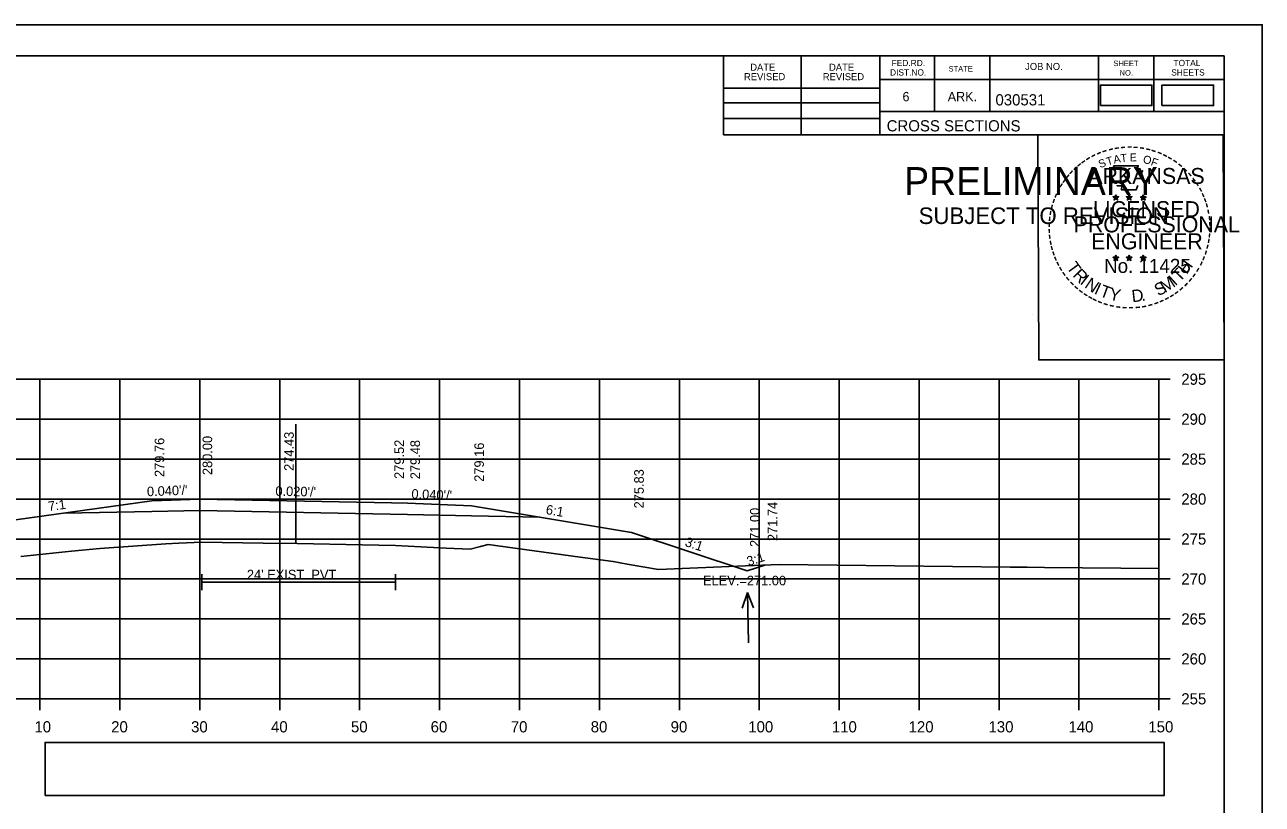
# Model space of a CAD drawing. Extents: x 285 to 4233, y -659 to 3710.
# Drawn here: x 1231.8 to 1386.6, y 288 to 385.6 of the extents above; entities that cross this region are included whole.
import ezdxf

# ---------------------------------------------------------------- set-up
doc = ezdxf.new("R2010")
doc.units = 0
for name, color, linetype in [('R_Alt Surface', 7, 'Continuous'), ('R_Axis', 7, 'Continuous'), ('R_Axis Annot', 7, 'Continuous'), ('R_Border', 7, 'Continuous'), ('R_Border PE', 7, 'Continuous'), ('R_Border Prem', 7, 'Continuous'), ('R_Exist Surface', 7, 'Continuous'), ('R_Fin Surface', 7, 'Continuous'), ('R_Grid', 7, 'Continuous'), ('R_No Plot', 7, 'Continuous'), ('R_Water', 7, 'Continuous'), ('R_Water Annot', 7, 'Continuous'), ('R_Xsect Elev', 7, 'Continuous'), ('R_Xsect Slope', 7, 'Continuous')]:
    doc.layers.add(name, color=color, linetype=linetype)

msp = doc.modelspace()

# ---------------------------------------------------------------- linework, layer by layer
at = {"layer": 'R_Alt Surface'}
for points in [[(1236.77, 324.46), (1247.68, 324.67), (1253.68, 324.79), (1253.68, 324.79), (1279.68, 324.27), (1287.68, 324.11), (1296.24, 323.94)], [(1253.95, 316.82), (1253.95, 314.82)], [(1278.15, 316.82), (1278.15, 314.82)], [(1253.95, 315.82), (1278.15, 315.82)]]:
    msp.add_lwpolyline(points, dxfattribs=at)
at = {"layer": 'R_Axis'}
for p, q in [((1373.68, 301.21), (1373.68, 341.21)), ((1375.08, 341.21), (1373.68, 341.21)), ((1375.08, 336.21), (1373.68, 336.21)), ((1375.08, 331.21), (1373.68, 331.21)), ((1375.08, 326.21), (1373.68, 326.21)), ((1375.08, 321.21), (1373.68, 321.21)), ((1375.08, 316.21), (1373.68, 316.21)), ((1375.08, 311.21), (1373.68, 311.21)), ((1375.08, 306.21), (1373.68, 306.21)), ((1073.68, 301.21), (1373.68, 301.21)), ((1233.68, 299.81), (1233.68, 301.21)), ((1243.68, 299.81), (1243.68, 301.21)), ((1253.68, 299.81), (1253.68, 301.21)), ((1263.68, 299.81), (1263.68, 301.21)), ((1273.68, 299.81), (1273.68, 301.21)), ((1283.68, 299.81), (1283.68, 301.21)), ((1293.68, 299.81), (1293.68, 301.21)), ((1303.68, 299.81), (1303.68, 301.21)), ((1313.68, 299.81), (1313.68, 301.21)), ((1323.68, 299.81), (1323.68, 301.21)), ((1333.68, 299.81), (1333.68, 301.21)), ((1343.68, 299.81), (1343.68, 301.21)), ((1353.68, 299.81), (1353.68, 301.21)), ((1363.68, 299.81), (1363.68, 301.21)), ((1373.68, 299.81), (1373.68, 301.21)), ((1375.08, 301.21), (1373.68, 301.21))]:
    msp.add_line(p, q, dxfattribs=at)
at = {"layer": 'R_Axis Annot'}
for points in [[(1366.36, 375.46), (1372.81, 375.46), (1372.81, 378.01), (1366.36, 378.01)], [(1374.05, 375.46), (1380.51, 375.46), (1380.51, 378.01), (1374.05, 378.01)], [(1234.32, 289.1), (1374.32, 289.1), (1374.32, 295.75), (1234.32, 295.75)]]:
    msp.add_lwpolyline(points, close=True, dxfattribs=at)
at = {"layer": 'R_Border'}
for p, q in [((1065.68, 381.67), (1381.86, 381.67)), ((1319.22, 371.79), (1319.22, 381.67)), ((1328.9, 371.79), (1328.9, 381.67)), ((1338.76, 381.67), (1338.76, 371.79)), ((1345.6, 381.67), (1345.6, 374.73)), ((1352.54, 381.67), (1352.54, 374.73)), ((1366.12, 381.67), (1366.12, 374.73)), ((1373.06, 381.67), (1373.06, 374.73)), ((1381.86, 176.21), (1381.86, 381.67)), ((1381.86, 378.73), (1338.76, 378.73)), ((1381.86, 378.75), (1381.86, 378.75)), ((1319.22, 377.65), (1338.76, 377.65)), ((1319.22, 375.79), (1338.76, 375.79)), ((1381.86, 374.73), (1338.76, 374.73)), ((1341.72, 374.73), (1381.86, 374.73)), ((1319.22, 373.85), (1338.76, 373.85)), ((1381.86, 371.79), (1319.22, 371.79))]:
    msp.add_line(p, q, dxfattribs=at)
at = {"layer": 'R_Border PE'}
for p, q in [((1367.94, 364.05), (1368.29, 363.94)), ((1367.94, 364.05), (1368.19, 364)), ((1367.94, 364.05), (1368.18, 363.92)), ((1368.07, 363.64), (1368.29, 363.94)), ((1368.07, 363.64), (1368.2, 363.88)), ((1368.07, 363.64), (1368.29, 363.86)), ((1368.29, 364.3), (1368.25, 364.05)), ((1368.29, 363.94), (1368.29, 364.3)), ((1368.29, 364.3), (1368.34, 364.05)), ((1368.64, 364.05), (1368.29, 363.94)), ((1368.5, 363.64), (1368.29, 363.94)), ((1368.64, 364.05), (1368.35, 364)), ((1368.5, 363.64), (1368.37, 363.93)), ((1368.64, 364.05), (1368.43, 363.94)), ((1369.61, 364.05), (1369.96, 363.94)), ((1369.61, 364.05), (1369.86, 364)), ((1369.61, 364.05), (1369.85, 363.92)), ((1369.74, 363.64), (1369.96, 363.94)), ((1369.74, 363.64), (1369.87, 363.88)), ((1369.74, 363.64), (1369.96, 363.86)), ((1369.96, 364.3), (1369.92, 364.05)), ((1369.96, 363.94), (1369.96, 364.3)), ((1369.96, 364.3), (1370.01, 364.05)), ((1370.31, 364.05), (1369.96, 363.94)), ((1370.17, 363.64), (1369.96, 363.94)), ((1370.31, 364.05), (1370.02, 364)), ((1370.17, 363.64), (1370.04, 363.93)), ((1370.31, 364.05), (1370.1, 363.94)), ((1371.38, 364.03), (1371.72, 363.92)), ((1371.38, 364.03), (1371.63, 363.99)), ((1371.38, 364.03), (1371.61, 363.91)), ((1371.51, 363.63), (1371.72, 363.92)), ((1371.51, 363.63), (1371.63, 363.87)), ((1371.72, 364.29), (1371.68, 364.04)), ((1371.72, 363.92), (1371.72, 364.29)), ((1371.72, 364.29), (1371.77, 364.04)), ((1372.07, 364.03), (1371.72, 363.92)), ((1371.94, 363.63), (1371.72, 363.92)), ((1372.07, 364.03), (1371.79, 363.99)), ((1371.94, 363.63), (1371.8, 363.92)), ((1372.07, 364.03), (1371.87, 363.93)), ((1368.5, 363.64), (1368.29, 363.85)), ((1370.17, 363.64), (1369.96, 363.85)), ((1371.51, 363.63), (1371.72, 363.84)), ((1371.94, 363.63), (1371.72, 363.84)), ((1367.94, 356.47), (1368.29, 356.36)), ((1367.94, 356.47), (1368.19, 356.43)), ((1367.94, 356.47), (1368.17, 356.35)), ((1368.07, 356.07), (1368.29, 356.36)), ((1368.07, 356.07), (1368.2, 356.31)), ((1368.07, 356.07), (1368.28, 356.28)), ((1368.29, 356.73), (1368.25, 356.48)), ((1368.5, 356.07), (1368.28, 356.28)), ((1368.29, 356.36), (1368.29, 356.73)), ((1368.29, 356.73), (1368.34, 356.48)), ((1368.63, 356.47), (1368.29, 356.36)), ((1368.5, 356.07), (1368.29, 356.36)), ((1368.63, 356.47), (1368.35, 356.42)), ((1368.5, 356.07), (1368.36, 356.36)), ((1368.63, 356.47), (1368.43, 356.37)), ((1369.61, 356.47), (1369.96, 356.36)), ((1369.61, 356.47), (1369.86, 356.43)), ((1369.61, 356.47), (1369.84, 356.35)), ((1369.74, 356.07), (1369.96, 356.36)), ((1369.74, 356.07), (1369.87, 356.31)), ((1369.74, 356.07), (1369.95, 356.28)), ((1369.96, 356.73), (1369.91, 356.48)), ((1370.17, 356.07), (1369.95, 356.28)), ((1369.96, 356.36), (1369.96, 356.73)), ((1369.96, 356.73), (1370, 356.48)), ((1370.3, 356.47), (1369.96, 356.36)), ((1370.17, 356.07), (1369.96, 356.36)), ((1370.3, 356.47), (1370.02, 356.42)), ((1370.17, 356.07), (1370.03, 356.36)), ((1370.3, 356.47), (1370.1, 356.37)), ((1371.37, 356.46), (1371.72, 356.35)), ((1371.37, 356.46), (1371.63, 356.42)), ((1371.37, 356.46), (1371.61, 356.34)), ((1371.51, 356.06), (1371.72, 356.35)), ((1371.51, 356.06), (1371.63, 356.3)), ((1371.51, 356.06), (1371.72, 356.27)), ((1371.72, 356.72), (1371.68, 356.47)), ((1371.72, 356.35), (1371.72, 356.72)), ((1371.72, 356.72), (1371.77, 356.47)), ((1372.07, 356.46), (1371.72, 356.35)), ((1371.94, 356.06), (1371.72, 356.35)), ((1371.94, 356.06), (1371.72, 356.27)), ((1372.07, 356.46), (1371.78, 356.41)), ((1371.94, 356.06), (1371.8, 356.35)), ((1372.07, 356.46), (1371.87, 356.36))]:
    msp.add_line(p, q, dxfattribs=at)
for points in [[(1367.98, 367.92), (1368.25, 367.1)], [(1371.49, 367), (1371.64, 367.29), (1370.95, 367.26), (1371.1, 367.92), (1367.98, 367.92)], [(1368.47, 365.5), (1368.47, 365.41), (1369.04, 365.4), (1368.98, 364.92), (1370.85, 364.92), (1371.05, 365.46)], [(1368.29, 364.3), (1368.5, 363.64), (1367.94, 364.05), (1368.64, 364.05), (1368.07, 363.64), (1368.29, 364.3)], [(1369.96, 364.3), (1370.17, 363.64), (1369.61, 364.05), (1370.31, 364.05), (1369.74, 363.64), (1369.96, 364.3)], [(1371.72, 364.29), (1371.94, 363.63), (1371.38, 364.03), (1372.07, 364.03), (1371.51, 363.63), (1371.72, 364.29)], [(1368.29, 356.73), (1368.5, 356.07), (1367.94, 356.47), (1368.63, 356.47), (1368.07, 356.07), (1368.29, 356.73)], [(1369.96, 356.73), (1370.17, 356.07), (1369.61, 356.47), (1370.3, 356.47), (1369.74, 356.07), (1369.96, 356.73)], [(1371.72, 356.72), (1371.94, 356.06), (1371.37, 356.46), (1372.07, 356.46), (1371.51, 356.06), (1371.72, 356.72)]]:
    msp.add_lwpolyline(points, dxfattribs=at)
for centre, radius in [((1368.29, 363.93), 0.172), ((1368.29, 363.93), 0.145), ((1368.29, 363.93), 0.116), ((1368.29, 363.93), 0.0991), ((1368.29, 363.93), 0.0747), ((1368.29, 363.93), 0.0495), ((1368.29, 363.93), 0.0296), ((1369.96, 363.93), 0.172), ((1369.96, 363.93), 0.145), ((1369.96, 363.93), 0.116), ((1369.96, 363.93), 0.0991), ((1369.96, 363.93), 0.0747), ((1369.96, 363.93), 0.0495), ((1369.96, 363.93), 0.0296), ((1371.72, 363.92), 0.172), ((1371.72, 363.92), 0.145), ((1371.72, 363.92), 0.116), ((1371.72, 363.92), 0.0991), ((1371.72, 363.92), 0.0747), ((1371.72, 363.92), 0.0495), ((1371.72, 363.92), 0.0296), ((1368.29, 356.36), 0.172), ((1368.29, 356.36), 0.145), ((1368.29, 356.36), 0.116), ((1368.29, 356.36), 0.0991), ((1368.29, 356.36), 0.0747), ((1368.29, 356.36), 0.0495), ((1368.29, 356.36), 0.0296), ((1369.95, 356.36), 0.172), ((1369.95, 356.36), 0.145), ((1369.95, 356.36), 0.116), ((1369.95, 356.36), 0.0991), ((1369.95, 356.36), 0.0747), ((1369.95, 356.36), 0.0495), ((1369.95, 356.36), 0.0296), ((1371.72, 356.35), 0.172), ((1371.72, 356.35), 0.145), ((1371.72, 356.35), 0.116), ((1371.72, 356.35), 0.0991), ((1371.72, 356.35), 0.0747), ((1371.72, 356.35), 0.0495), ((1371.72, 356.35), 0.0296)]:
    msp.add_circle(centre, radius, dxfattribs=at)
at = {"layer": 'R_Exist Surface'}
msp.add_lwpolyline([(1231.27, 319.03), (1237.63, 319.67), (1241.17, 320.01), (1249.41, 320.6), (1251.07, 320.67), (1253.95, 320.82), (1261.61, 320.7), (1265.87, 320.64), (1274.01, 320.47), (1278.15, 320.39), (1284.52, 320.08), (1287.49, 319.94), (1288.81, 320.27), (1289.74, 320.53), (1301.27, 318.93), (1305.39, 318.39), (1307.13, 318.07), (1311.06, 317.41), (1320.92, 317.8), (1326.2, 318.02), (1355.05, 317.7), (1357.2, 317.67), (1359.35, 317.65), (1373.68, 317.53)], dxfattribs=at)
at = {"layer": 'R_Fin Surface'}
msp.add_lwpolyline([(1211.58, 318.61), (1223.68, 322.64), (1247.68, 325.97), (1253.68, 326.21), (1277.68, 325.73), (1279.68, 325.69), (1287.68, 325.37), (1307.68, 322.04), (1322.17, 317.21), (1324.39, 317.95)], dxfattribs=at)
at = {"layer": 'R_Grid'}
for p, q in [((1073.68, 341.21), (1373.68, 341.21)), ((1233.68, 301.21), (1233.68, 341.21)), ((1243.68, 301.21), (1243.68, 341.21)), ((1253.68, 301.21), (1253.68, 341.21)), ((1263.68, 301.21), (1263.68, 341.21)), ((1273.68, 301.21), (1273.68, 341.21)), ((1283.68, 301.21), (1283.68, 341.21)), ((1293.68, 301.21), (1293.68, 341.21)), ((1303.68, 301.21), (1303.68, 341.21)), ((1313.68, 301.21), (1313.68, 341.21)), ((1323.68, 301.21), (1323.68, 341.21)), ((1333.68, 301.21), (1333.68, 341.21)), ((1343.68, 301.21), (1343.68, 341.21)), ((1353.68, 301.21), (1353.68, 341.21)), ((1363.68, 301.21), (1363.68, 341.21)), ((1373.68, 301.21), (1373.68, 341.21)), ((1073.68, 336.21), (1373.68, 336.21)), ((1073.68, 331.21), (1373.68, 331.21)), ((1073.68, 326.21), (1373.68, 326.21)), ((1073.68, 321.21), (1373.68, 321.21)), ((1073.68, 316.21), (1373.68, 316.21)), ((1073.68, 311.21), (1373.68, 311.21)), ((1073.68, 306.21), (1373.68, 306.21)), ((1073.68, 301.21), (1373.68, 301.21))]:
    msp.add_line(p, q, dxfattribs=at)
at = {"layer": 'R_No Plot'}
for p, q in [((1053.28, 385.57), (1386.61, 385.57)), ((1357.89, 349.34), (1357.89, 349.34))]:
    msp.add_line(p, q, dxfattribs=at)
for points in [[(1053.27, 385.57), (1386.61, 385.57), (1386.61, 172.23), (1053.27, 172.23)], [(1299.6, 381.67), (1319.22, 381.67), (1319.22, 371.79), (1335.33, 371.79), (1358.53, 371.79), (1358.65, 343.63), (1381.86, 343.63), (1381.86, 176.21), (1065.68, 176.21), (1065.68, 381.67)], [(1358.53, 371.79), (1381.74, 371.79), (1381.86, 343.63), (1358.65, 343.63)]]:
    msp.add_lwpolyline(points, close=True, dxfattribs=at)
at = {"layer": 'R_Water Annot'}
for p, q in [((1322.22, 314.51), (1321.55, 312.57)), ((1322.31, 308.22), (1322.22, 314.51)), ((1322.22, 314.51), (1322.95, 312.59))]:
    msp.add_line(p, q, dxfattribs=at)
at = {"layer": 'R_Xsect Elev'}
msp.add_line((1265.68, 320.64), (1265.68, 335.57), dxfattribs=at)

# ---------------------------------------------------------------- texts
at = {"layer": 'R_Axis Annot'}
for s, p in [('295', (1376.48, 340.51)), ('290', (1376.48, 335.51)), ('285', (1376.48, 330.51)), ('280', (1376.48, 325.51)), ('275', (1376.48, 320.51)), ('270', (1376.48, 315.51)), ('265', (1376.48, 310.51)), ('260', (1376.48, 305.51)), ('255', (1376.48, 300.51)), ('10', (1232.99, 297.01)), ('20', (1242.59, 297.01)), ('30', (1252.59, 297.01)), ('40', (1262.59, 297.01)), ('50', (1272.59, 297.01)), ('60', (1282.56, 297.01)), ('70', (1292.59, 297.01)), ('80', (1302.59, 297.01)), ('90', (1312.59, 297.01)), ('100', (1322.3, 297.01)), ('110', (1332.76, 297.01)), ('120', (1342.36, 297.01)), ('130', (1352.36, 297.01)), ('140', (1362.36, 297.01)), ('150', (1372.36, 297.01))]:
    msp.add_text(s, height=1.4, dxfattribs=at).set_placement(p)
at = {"layer": 'R_Border'}
for s, height, p in [('FED.RD.', 0.782, (1340.24, 380.39)), ('SHEET', 0.684, (1367.98, 380.39)), ('TOTAL', 0.782, (1375.5, 380.39)), ('REVISED', 0.879, (1321.77, 378.63)), ('DATE', 0.879, (1322.55, 379.81)), ('REVISED', 0.879, (1331.63, 378.63)), ('DATE', 0.879, (1332.41, 379.81)), ('DIST.NO.', 0.782, (1340.04, 379.21)), ('STATE', 0.684, (1347.36, 379.71)), ('JOB NO.', 0.879, (1356.94, 379.91)), ('NO.', 0.684, (1368.76, 379.21)), ('SHEETS', 0.782, (1375.22, 379.21)), ('6', 1.17, (1341.6, 375.99)), ('ARK.', 1.172, (1347.26, 375.99)), ('030531', 1.4, (1353.23, 375.47)), ('CROSS SECTIONS', 1.4, (1339.62, 372.22))]:
    msp.add_text(s, height=height, rotation=360, dxfattribs=at).set_placement(p)
at = {"layer": 'R_Border PE'}
for s, height, rotation, p in [('-', 1.6, 13.6301, (1367.48, 369.29)), ('-', 1.6, 10.2193, (1368.16, 369.45)), ('-', 1.6, 5.8968, (1368.89, 369.56)), ('-', 1.6, 0.1862, (1369.66, 369.64)), ('-', 1.6, 357.743, (1370.38, 369.62)), ('-', 1.6, 352.1617, (1371.13, 369.57)), ('-', 1.6, 347.2049, (1371.85, 369.45)), ('-', 1.6, 36.2317, (1364.29, 367.7)), ('-', 1.6, 34.0636, (1364.87, 368.1)), ('-', 1.6, 28.7918, (1365.46, 368.47)), ('-', 1.6, 24.3072, (1366.1, 368.78)), ('S', 1, 21.594, (1366.34, 367.6)), ('-', 1.6, 19.1761, (1366.73, 369.05)), ('T', 1, 16.4036, (1367.25, 367.93)), ('A', 1, 11.2132, (1368.08, 368.18)), ('T', 1, 6.0228, (1368.93, 368.35)), ('E', 1, 0.8323, (1370.03, 368.46)), ('O', 1, 350.4515, (1371.64, 368.25)), ('F', 1, 340.0707, (1372.59, 368.02)), ('-', 1.6, 342.3362, (1372.48, 369.3)), ('-', 1.6, 337.8551, (1373.22, 369.08)), ('-', 1.6, 334.1211, (1373.85, 368.8)), ('-', 1.6, 329.6409, (1374.43, 368.52)), ('-', 1.6, 325.8627, (1375.07, 368.16)), ('-', 1.6, 48.423, (1362.93, 366.43)), ('-', 1.6, 42.9622, (1363.38, 366.91)), ('-', 1.6, 38.9507, (1363.81, 367.32)), ('ARKANSAS', 2, 360, (1364.84, 365.64)), ('-', 1.6, 320.5297, (1375.68, 367.73)), ('-', 1.6, 315.5786, (1376.28, 367.25)), ('-', 1.6, 309.8797, (1376.85, 366.7)), ('-', 1.6, 58.0706, (1361.79, 364.85)), ('-', 1.6, 54.2325, (1362.12, 365.37)), ('-', 1.6, 50.6142, (1362.53, 365.94)), ('-', 1.6, 306.6522, (1377.37, 366.09)), ('-', 1.4, 303.6753, (1377.86, 365.53)), ('-', 1.6, 67.7743, (1361.22, 363.62)), ('-', 1.6, 62.8713, (1361.48, 364.23)), ('DWB', 0.01, 360, (1368.28, 363.93)), ('DWB', 0.01, 360, (1369.95, 363.93)), ('DWB', 0.01, 360, (1371.71, 363.92)), ('-', 1.6, 299.6684, (1378.18, 364.92)), ('-', 1.6, 294.6628, (1378.5, 364.31)), ('-', 1.6, 290.5728, (1378.76, 363.73)), ('-', 1.6, 75.461, (1360.8, 362.28)), ('-', 1.6, 72.3945, (1361, 362.99)), ('LICENSED', 2, 360, (1365.43, 361.49)), ('-', 1.6, 285.1233, (1378.99, 363.15)), ('-', 1.6, 280.5493, (1379.19, 362.41)), ('-', 1.6, 89.0622, (1360.57, 360.17)), ('-', 1.6, 85.1863, (1360.59, 360.87)), ('-', 1.6, 81.2013, (1360.67, 361.57)), ('PROFESSIONAL', 2, 360, (1363.01, 359.58)), ('-', 1.6, 276.5962, (1379.35, 361.64)), ('-', 1.6, 274.3301, (1379.41, 360.92)), ('-', 1.6, 94.1959, (1360.6, 359.45)), ('-', 1.6, 98.9479, (1360.68, 358.78)), ('ENGINEER', 2, 360, (1365.2, 357.46)), ('-', 1.6, 263.5172, (1379.43, 359.62)), ('-', 1.6, 269.9407, (1379.45, 360.29)), ('-', 1.6, 101.7149, (1360.81, 358.05)), ('-', 1.6, 105.4578, (1360.97, 357.45)), ('-', 1.6, 255.7626, (1379.25, 358.29)), ('-', 1.6, 260.9953, (1379.36, 358.97)), ('-', 1.6, 109.0874, (1361.19, 356.82)), ('-', 1.6, 114.0643, (1361.44, 356.23)), ('No. 11425', 1.757, 360, (1366.82, 354.51)), ('DWB', 0.01, 360, (1368.27, 356.36)), ('DWB', 0.01, 360, (1369.94, 356.36)), ('DWB', 0.01, 360, (1371.71, 356.35)), ('H', 1.54, 54.6088, (1377.17, 354.24)), ('-', 1.6, 247.8887, (1378.84, 356.9)), ('-', 1.6, 252.8681, (1379.07, 357.57)), ('-', 1.6, 115.7289, (1361.75, 355.61)), ('-', 1.6, 120.4471, (1362.1, 355.02)), ('-', 1.6, 125.8934, (1362.51, 354.46)), ('T', 1.54, 306.0406, (1362.05, 355.2)), ('R', 1.54, 314.005, (1362.81, 354.15)), ('T', 1.54, 46.6444, (1376.28, 353.29)), ('-', 1.6, 239.0712, (1378.19, 355.51)), ('-', 1.6, 244.6197, (1378.58, 356.27)), ('-', 1.6, 130.7181, (1362.97, 353.91)), ('-', 1.6, 134.2238, (1363.49, 353.36)), ('I', 1.54, 321.9694, (1363.71, 353.22)), ('N', 1.54, 326.5002, (1364.28, 352.75)), ('I', 1.54, 335.3603, (1365.48, 351.96)), ('T', 1.54, 339.8912, (1366.15, 351.64)), ('S', 1.54, 26.9312, (1373.59, 351.56)), ('M', 1.54, 32.6563, (1374.43, 351.97)), ('I', 1.54, 42.1136, (1375.72, 352.82)), ('-', 1.6, 225.7653, (1376.88, 353.73)), ('-', 1.6, 231.2538, (1377.36, 354.3)), ('-', 1.6, 233.8452, (1377.79, 354.86)), ('-', 1.6, 138.9338, (1364.01, 352.9)), ('-', 1.6, 144.6463, (1364.57, 352.49)), ('-', 1.6, 148.0898, (1365.13, 352.12)), ('-', 1.6, 151.5704, (1365.71, 351.8)), ('Y', 1.54, 347.8556, (1367.36, 351.19)), ('D', 1.54, 6.3969, (1370.35, 350.83)), ('-', 1.6, 207.3568, (1374.71, 352.02)), ('-', 1.6, 212.2491, (1375.27, 352.36)), ('-', 1.6, 215.7363, (1375.81, 352.75)), ('-', 1.6, 221.0851, (1376.35, 353.22)), ('-', 1.6, 154.6002, (1366.23, 351.55)), ('-', 1.6, 158.5612, (1366.85, 351.3)), ('-', 1.6, 162.7983, (1367.54, 351.08)), ('-', 1.6, 167.5555, (1368.26, 350.92)), ('-', 1.6, 173.1155, (1369.03, 350.81)), ('-', 1.6, 176.5183, (1369.78, 350.76)), ('-', 1.6, 181.5918, (1370.52, 350.78)), ('-', 1.6, 185.8167, (1371.33, 350.85)), ('-', 1.6, 191.2858, (1372.06, 350.98)), ('.', 1.54, 13.7642, (1371.54, 350.96)), ('-', 1.6, 195.4743, (1372.79, 351.18)), ('-', 1.6, 200.7184, (1373.47, 351.43)), ('-', 1.6, 204.2516, (1374.09, 351.7))]:
    msp.add_text(s, height=height, rotation=rotation, dxfattribs=at).set_placement(p)
at = {"layer": 'R_Border Prem'}
for s, height, p in [('PRELIMINARY', 3.5, (1341.81, 364.25)), ('DWB', 0.01, (1342.55, 366.1)), ('SUBJECT TO REVISION', 2.0751, (1343.62, 360.63))]:
    msp.add_text(s, height=height, rotation=360, dxfattribs=at).set_placement(p)
at = {"layer": 'R_Water'}
msp.add_text("24' EXIST. PVT.", height=1.2, dxfattribs=at).set_placement((1259.57, 316.16))
at = {"layer": 'R_Xsect Elev'}
for s, p in [('274.43', (1265.44, 329.73)), ('279.76', (1249.23, 328.97)), ('280.00', (1255.23, 329.21)), ('279.52', (1279.23, 328.73)), ('279.48', (1281.23, 328.69)), ('279.16', (1289.23, 328.37)), ('275.83', (1309.23, 325.04)), ('271.74', (1325.94, 320.95)), ('271.00', (1323.72, 320.21))]:
    msp.add_text(s, height=1.2, rotation=90, dxfattribs=at).set_placement(p)
msp.add_text('ELEV.=271.00', height=1.2, dxfattribs=at).set_placement((1316.64, 315.41))
at = {"layer": 'R_Xsect Slope'}
for s, rotation, p in [("0.040'/'", 2.2906, (1247.09, 326.55)), ("0.020'/'", 358.8542, (1263.13, 326.62)), ("0.040'/'", 357.7096, (1280.14, 326.27)), ('7:1', 7.9062, (1234.78, 324.69)), ('6:1', 350.5386, (1296.91, 324.34)), ('3:1', 341.5619, (1314.29, 320.36)), ('3:1', 18.4287, (1322.34, 317.79))]:
    msp.add_text(s, height=1.2, rotation=rotation, dxfattribs=at).set_placement(p)

doc.saveas('drawing.dxf')
